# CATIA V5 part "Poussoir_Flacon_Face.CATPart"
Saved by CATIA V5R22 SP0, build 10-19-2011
Part number: Poussoir_Flacon_Face
Bounding box of the stored display mesh (mm): x -20 to 20, y 0 to 5, z -24.5 to 24.5
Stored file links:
  C:\Users\La forge\Desktop\CAO_PER_pick&place_2023A\Sous_Ensemble_Flacon\Verin\Poussoir_Flacon\Poussoir_Flacon_Face.CATPart
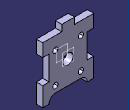
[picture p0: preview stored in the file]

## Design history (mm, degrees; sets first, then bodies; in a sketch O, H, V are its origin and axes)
Body1 (main body)
  Sketch1 on zx-plane, origin (0, 0, 0), H (-1, 0, 0), V (0, 0, 1)
    line L1 (20, -24.5) -> (15, -24.5)
    line L2 (-20, -24.5) -> (-20, 24.5)
    line L3 (-20, 24.5) -> (20, 24.5)
    line L4 (20, 24.5) -> (20, -24.5)
    point P5 (15, -24.5)
    line L5 (-15, -24.5) -> (-15, -24.5)
    line L6 (-10, -19.5) -> (10, -19.5)
    line L7 (15, -24.5) -> (15, -24.5)
    point P7 (15, -19.5)
    arc A1 centre (-10, -24.5) radius 5 from (-15, -24.5) to (-10, -19.5) cw
    arc A2 centre (10, -24.5) radius 5 from (10, -19.5) to (15, -24.5) cw
    line L8 (-15, -24.5) -> (-20, -24.5)
    length L4 = 49
    length L3 = 40
    distance L7 L4 = 5
    radius A1 = 5
    distance P7 P5 = 5
    radius A2 = 5
    horizontal: L1 H, L3 H, L6 H, L8 H
    vertical: L2 V, L4 V, L5 V, L7 V
    equidistance: L4 L2 O, L1 L3 O, L7 L5 O
    tangency: A1 L5, A1 L6, A2 L6, A2 L7
    coincidence: L6 P7, L7 P7, L1 L8
  Pad1: profile Sketch1, direction (0, 1, 0), length 5
  Sketch2 on end face of Pad1, origin (0, 5, 0), H (-1, 0, 0), V (0, 0, 1)
    point P1 (-15, 9.5)
    line L1 (-15, 9.5) -> (-20, 9.5)
    line L2 (-20, 9.5) -> (-20, -9.5)
    line L3 (-20, -9.5) -> (-15, -9.5)
    line L4 (-15, -9.5) -> (-15, 9.5)
    point P2 (-20, 9.5)
    point P3 (-20, -9.5)
    point P4 (-15, -9.5)
    reference projected line E1 (-20, 24.5) -> (-20, -24.5) from edge [face of Pad1 from Sketch1.L2 | end face of Pad1]
    reference projected line E2 (-20, -24.5) -> (-15, -24.5) from edge [face of Pad1 from Sketch1.L8 | end face of Pad1]
    point P5 (15, 9.5)
    point P6 (20, 9.5)
    point P7 (20, -9.5)
    point P8 (15, -9.5)
    line L5 (15, 9.5) -> (20, 9.5)
    line L6 (20, 9.5) -> (20, -9.5)
    line L7 (20, -9.5) -> (15, -9.5)
    line L8 (15, -9.5) -> (15, 9.5)
    distance L3 E2 = 15
    length L4 = 19
    length L1 = 5
    horizontal: L1 H, L3 H
    vertical: L2 V, L4 V
    coincidence: L2 E1
    symmetry: P1 P5 V, P2 P6 V, P3 P7 V, P4 P8 V, L1 L5 V, L2 L6 V, L3 L7 V, L4 L8 V
  Pocket1: profile Sketch2, direction (0, -1, 0), through (limit type 6)
  Sketch3 on end face of Pad1, origin (0, 5, 0), H (-1, 0, 0), V (0, 0, 1)
    point P1 (-5, 24.5)
    line L1 (-5, 24.5) -> (-20, 24.5)
    line L2 (-20, 24.5) -> (-20, 19.5)
    line L3 (-20, 19.5) -> (-5, 19.5)
    line L4 (-5, 19.5) -> (-5, 24.5)
    point P2 (-20, 24.5)
    point P3 (-20, 19.5)
    point P4 (-5, 19.5)
    reference projected line E1 (20, 24.5) -> (-20, 24.5) from edge [face of Pad1 from Sketch1.L3 | end face of Pad1]
    reference projected line E2 (-20, 24.5) -> (-20, -24.5) from edge [face of Pad1 from Sketch1.L2 | end face of Pad1]
    point P5 (5, 24.5)
    point P6 (20, 24.5)
    point P7 (20, 19.5)
    point P8 (5, 19.5)
    line L5 (5, 24.5) -> (20, 24.5)
    line L6 (20, 24.5) -> (20, 19.5)
    line L7 (20, 19.5) -> (5, 19.5)
    line L8 (5, 19.5) -> (5, 24.5)
    length L4 = 5
    length L3 = 15
    horizontal: L1 H, L3 H
    vertical: L2 V, L4 V
    coincidence: L1 E1, L2 E2
    symmetry: P1 P5 V, P2 P6 V, P3 P7 V, P4 P8 V, L1 L5 V, L2 L6 V, L3 L7 V, L4 L8 V
  Pocket2: profile Sketch3, direction (0, -1, 0), through (limit type 6)
  Sketch4 on zx-plane, origin (0.1806, 0, -1.3541), H (1, 0, 0), V (0, 0, -1)
    point P1 (0, 0)
  Hole1: placed by Sketch4, at (0.1806, 0, -1.3541) direction (0, 1, 0), diameter 8, depth 12
  Plane1: type Offset, RefPlane zx-plane, Offset 5
  Sketch5 on end face of Pad1, origin (-16.3919, 5, 18.6806), H (1, 0, 0), V (0, 0, -1)
    point P1 (6.3919, 9.1806)
    reference projected line E1 (11.3919, -0.8194) -> (-3.6081, -0.8194) from edge [end face of Pad1 | face of Pocket2 from Sketch3.L7]
    reference projected line E2 (-3.6081, 43.1806) -> (-3.6081, -5.8194) from edge [face of Pad1 from Sketch1.L4 | end face of Pad1]
    distance P1 E1 = 10
    distance P1 E2 = 10
  Hole2: placed by Sketch5, at (-10, 5, 9.5) direction (0, -1, 0), diameter 4.134, through (limit type 3), threaded "M5", thread diameter 5, thread depth 5, pitch 0.8
  RectPattern1: of Hole2, direction 1 instances 2, spacing 20, along end face of Pad1 reversed, direction 2 instances 2, spacing 24, along end face of Pad1 reversed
